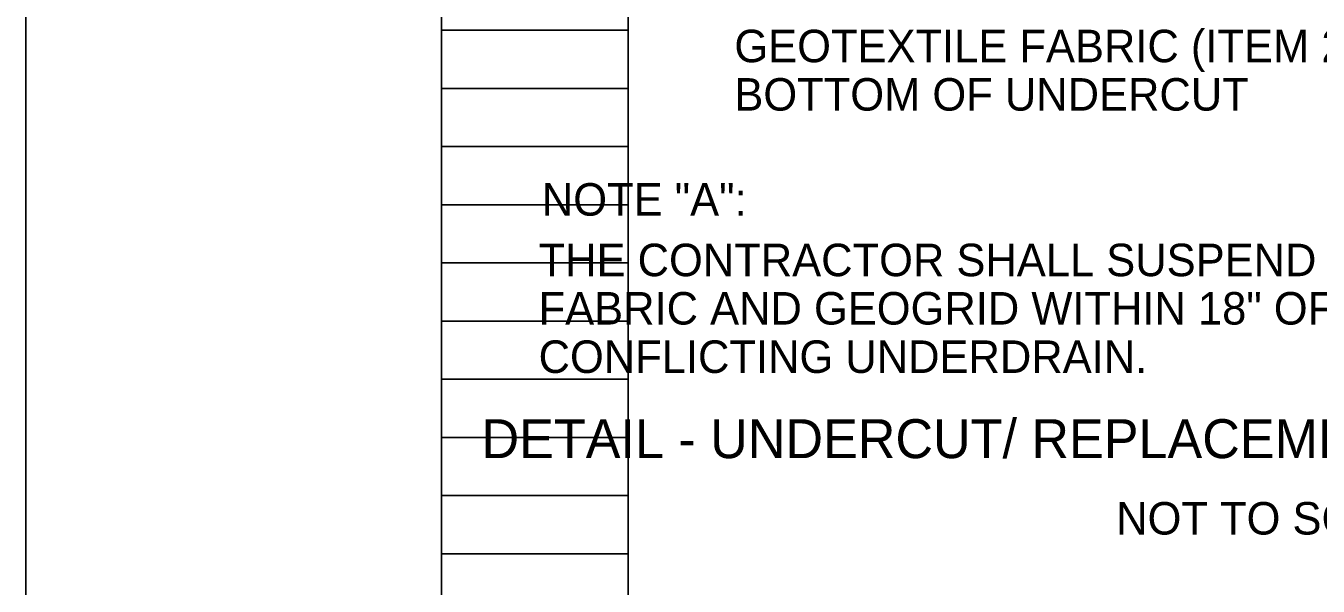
# Model space of a CAD drawing. Extents: x 0 to 34, y 0 to 22.
# Drawn here: x 0 to 6.22, y 10.9 to 13.6 of the extents above; entities that cross this region are included whole.
import ezdxf

# ---------------------------------------------------------------- set-up
doc = ezdxf.new("R2010")
doc.units = 0
for name, color, linetype in [('Default', 7, 'Continuous'), ('SC_Scratch1', 7, 'Continuous'), ('SH_Border', 7, 'Continuous'), ('SH_Cut_Line', 7, 'Continuous'), ('TX_P_1', 7, 'Continuous')]:
    doc.layers.add(name, color=color, linetype=linetype)

msp = doc.modelspace()

# ---------------------------------------------------------------- linework, layer by layer
at = {"layer": 'SC_Scratch1'}
for p, q in [((2, 0.98), (2, 21.14)), ((2.9, 0.98), (2.9, 21.14)), ((2, 13.58), (2.9, 13.58)), ((2, 13.3), (2.9, 13.3)), ((2, 13.02), (2.9, 13.02)), ((2, 12.74), (2.9, 12.74)), ((2, 12.46), (2.9, 12.46)), ((2, 12.18), (2.9, 12.18)), ((2, 11.9), (2.9, 11.9)), ((2, 11.62), (2.9, 11.62)), ((2, 11.34), (2.9, 11.34)), ((2, 11.06), (2.9, 11.06))]:
    msp.add_line(p, q, dxfattribs=at)
at = {"layer": 'SH_Border'}
msp.add_lwpolyline([(2, 21.5), (33.5, 21.5), (33.5, 0.5), (2, 0.5)], close=True, dxfattribs=at)
at = {"layer": 'SH_Cut_Line'}
msp.add_lwpolyline([(0, 0), (34, 0), (34, 22), (0, 22)], close=True, dxfattribs=at)

# ---------------------------------------------------------------- texts
at = {"layer": 'Default'}
for s, height, p in [('GEOTEXTILE FABRIC (ITEM 204) AT ', 0.156486, (3.4104, 13.4262)), ('BOTTOM OF UNDERCUT', 0.156486, (3.4104, 13.1933)), ('NOTE "A":', 0.15649, (2.4837, 12.6876)), ('THE CONTRACTOR SHALL SUSPEND THE USE OF GEOTEXTILE ', 0.156486, (2.4681, 12.3962)), ('FABRIC AND GEOGRID WITHIN 18" OF EITHER SIDE OF A ', 0.156486, (2.4681, 12.1634)), ('CONFLICTING UNDERDRAIN. ', 0.156486, (2.4681, 11.9305)), ('NOT TO SCALE', 0.156486, (5.2484, 11.1525))]:
    msp.add_text(s, height=height, rotation=359.99999, dxfattribs=at).set_placement(p)
at = {"layer": 'TX_P_1'}
msp.add_text('DETAIL - UNDERCUT/ REPLACEMENT TREATMENT METHOD', height=0.1875, rotation=359.99999, dxfattribs=at).set_placement((2.1935, 11.5202))

doc.saveas('drawing.dxf')
